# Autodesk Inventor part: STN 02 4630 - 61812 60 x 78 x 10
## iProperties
Created: 2005-03
Part Number: STN 02 4630 - 61812 60 x 78 x 10
Material: Steel, Mild
Description: Deep Groove Ball Bearing
Vendor: Autodesk Inc.
Document SubType Name: Modeling
Standard: STN 02 4630
Designer: brent
Standards Organization: STN
Language: en-US
Size Designation: 61812 60 x 78 x 10
Categories: <MemberInstance Version="R10.0.0"><Categories><Category DisplayName="Shaft Parts" InternalName="7f7aeb1f-a693-4053-b835-cee3144e0d98" Mnemonic="SHFT"><Category
Density: 1 g/cm^3
Author: brent
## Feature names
1. Body [Revolution]
2. Fillet1
3. Ball [Revolution]
4. Balls [Circular Pattern]
